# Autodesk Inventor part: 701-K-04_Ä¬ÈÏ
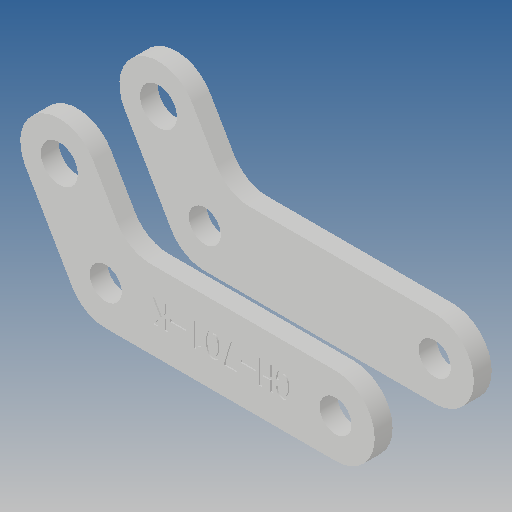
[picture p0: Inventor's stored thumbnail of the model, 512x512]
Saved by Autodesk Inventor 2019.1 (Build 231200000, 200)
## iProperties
Created: 2010-06
Part Number: 701-K-04_Ä¬ÈÏ
Material: Ogólny
Document SubType Name: Modeling
Designer: CADENGINEERING4
Density: 1 g/cm^3
Appearance: Domyślna
Author: CADENGINEERING4
Revision Number: ÈÎºÎ
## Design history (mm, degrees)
feature "NONE"
feature "NONE:1"
node "Bryła1"
node "Bryła2"
